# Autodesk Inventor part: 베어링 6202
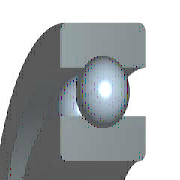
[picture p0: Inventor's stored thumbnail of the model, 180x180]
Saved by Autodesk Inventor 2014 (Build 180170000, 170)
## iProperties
Created: 2015-12
Part Number: 베어링 6202
Material: 강철, 연강
Description: 깊은 그루브 볼 베어링
Document SubType Name: Modeling
Standard: KS B 2023
Designer: mdu
Standards Organization: KS
Language: ko-KR
Size Designation: 6202 - 15 x 35 x 11
Categories: <MemberInstance><Categories><Category DisplayName="샤프트 부품" InternalName="7f7aeb1f-a693-4053-b835-cee3144e0d98" Mnemonic="SHFT"><Category DisplayName="베어링" Inter
Density: 7.86 g/cm^3
Mass: 45.8725 g
Surface Area: 51.5584 cm^2
Volume: 5.83619 cm^3
Appearance: 강철
Company: 한국ATC센터
IsCustomPart: 1
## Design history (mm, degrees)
sketch "스케치" dims "d0" = 5.2 (= -0.26 x WD + 0.26 x BD)
  geometry: L1 (2.9, 12.5)-(8.1, 12.5); L2 (5.5, 12.5)-(5.5, 9.9); L3 (5.5, 12.5)-(5.5, 15.1); L4 (3.568, 10.76)-(0, 10.76); L5 (0, 7.5)-(11, 7.5); L6 (3.568, 14.24)-(0, 14.24); L7 (0, 17.5)-(11, 17.5); L8 (11, 7.5)-(11, 10.76); L9 (7.432, 10.76)-(11, 10.76); L10 (7.432, 14.24)-(11, 14.24); L11 (11, 17.5)-(11, 14.24); L12 (-1.4, 0)-(8.4, 0) reference; L13 (0, -0.3)-(0, 5.3) reference
  constraints: 22 end point, 4 point on line, 2 collinear, 2 perpendicular, 2 symmetric about line, 1 midpoint, 1 parallel, 14 other
  dimensions: "d9" = 15 diameter of L5 L12 (= WD); "d11" = 35 diameter of L7 L12 (= BD); "d12" = 11 distance between parallel lines of L8 L13 (= KB); "d13" = 21.52 diameter of L9 L12 (= 0.326 x BD + 0.674 x WD)
revolve "본체" stored, may be unused: angle "d6" = 90 deg
revolve "볼" stored, may be unused: angle "d7" = 90 deg
pattern_circular "IDS_ARRAYBALL[SIMPL:T]" dims angle "d3" = 360 deg
body "Solid1"
fillet "모깎기1" dims "d1" = 0.6 (= KRS)
other parameters: "WD" = 15 [user parameter; used in 5 equation terms], "BD" = 35 [user parameter; used in 5 equation terms], "KB" = 11 [user parameter; used in 1 equation term], "KRS" = 0.6 [user parameter; used in 1 equation term], "d4" = 0, "d5" = 0, "d8" = 0, "d14" = 0, "d15" = 0, "BBA" = 0 [user parameter], "BC0" = 3750000 [user parameter], "BC" = 7800000 [user parameter], "BR" = 17.5 (= 0.5 x BD) [user parameter], "WR" = 7.5 (= 0.5 x WD) [user parameter]
